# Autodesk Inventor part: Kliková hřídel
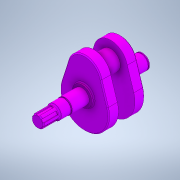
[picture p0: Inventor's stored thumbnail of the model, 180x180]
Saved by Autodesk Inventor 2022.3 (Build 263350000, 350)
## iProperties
Created: 2025-11
Part Number: Kliková hřídel
Material: Všeobecné
Description: STEP AP203
Document SubType Name: Modeling
Designer: Hra42
Density: 1 g/cm^3
Appearance: Výchozí(1)
Title: Kliková høídel.STEP
Revision Number: LIBOVOLNÃ
Sending System: SolidWorks 2024
Preprocessor: SwSTEP 2.0
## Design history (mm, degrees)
feature "Kliková hřídel.ipt_1_"
node "Těleso1"
